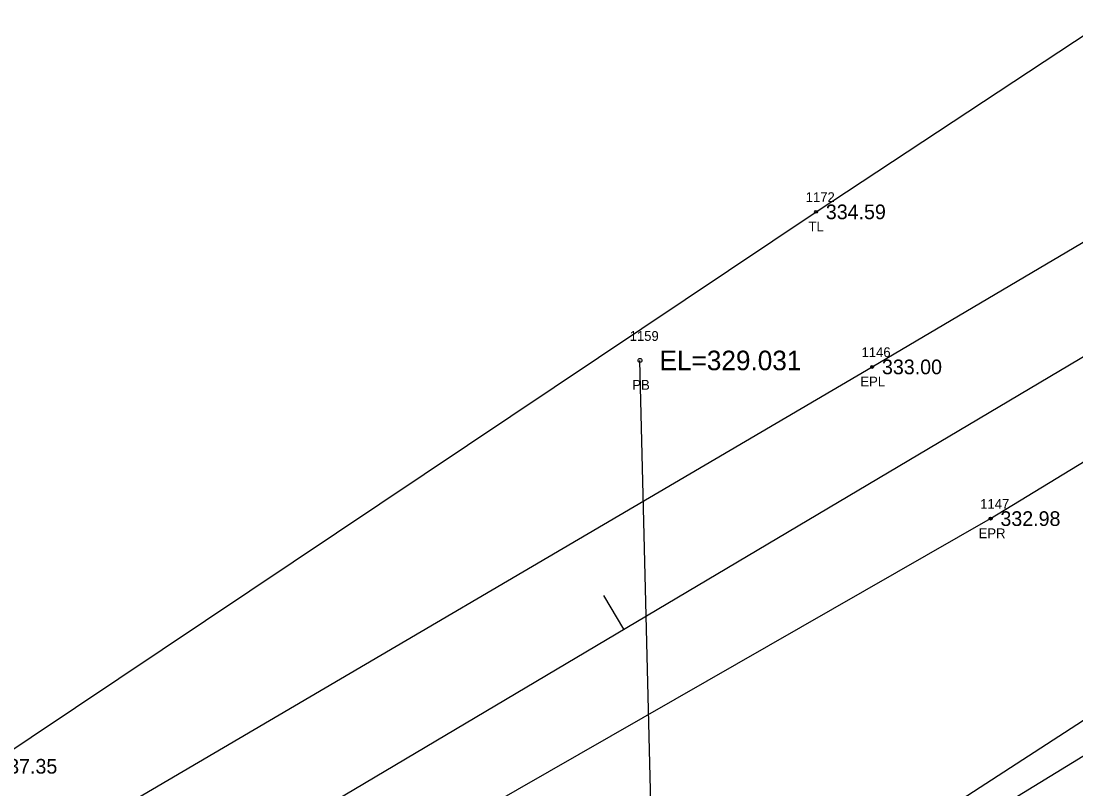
# Model space of a CAD drawing. Extents: x 2231119 to 2232595, y 1035731 to 1037094.
# Drawn here: x 2231678 to 2231785.8, y 1036525.6 to 1036604.1 of the extents above; entities that cross this region are included whole.
import ezdxf

# ---------------------------------------------------------------- set-up
doc = ezdxf.new("R2010")
doc.units = 0
for name, color, linetype in [('RD_EX_DR_Pipe', 7, 'Continuous'), ('RD_EX_DR_Pipe_txCode', 7, 'Continuous'), ('RD_EX_Fence_Other', 7, 'Continuous'), ('RD_EX_Road', 7, 'Continuous'), ('RD_EX_Road_txCode', 7, 'Continuous'), ('RD_EX_TX_Road_ELEV', 7, 'Continuous'), ('RD_EX_TX_VEG_ELEV', 7, 'Continuous'), ('RD_EX_VEG', 7, 'Continuous'), ('RD_EX_VEG_txCode', 7, 'Continuous'), ('RD_HC_Cl', 7, 'Continuous'), ('RD_HC_Data_Tic', 7, 'Continuous'), ('RD_SMD_Locator', 7, 'Continuous'), ('RD_TX_Pipe_ElevEX', 7, 'Continuous')]:
    doc.layers.add(name, color=color, linetype=linetype)

msp = doc.modelspace()

# ---------------------------------------------------------------- linework, layer by layer
at = {"layer": 'RD_EX_DR_Pipe'}
msp.add_lwpolyline([(2231761.49, 1036500.4), (2231742.72, 1036515.42), (2231742.56, 1036515.9), (2231741.25, 1036569.44)], dxfattribs=at)
at = {"layer": 'RD_EX_Fence_Other'}
msp.add_lwpolyline([(2231742.82, 1036485.51), (2231730.99, 1036494.96), (2231789.88, 1036531.02), (2231876.81, 1036583.89), (2231964.37, 1036635.23), (2232046.18, 1036684.79), (2232133.57, 1036734.4), (2232210.6, 1036793.49), (2232301.78, 1036835.03)], dxfattribs=at)
at = {"layer": 'RD_EX_Road'}
for points in [[(2231606.1, 1036462.92), (2231601.27, 1036470.82), (2231681.58, 1036519.84), (2231764.99, 1036568.78), (2231851.5, 1036619.95), (2231935.62, 1036669.65), (2232021.78, 1036720.22), (2232106.75, 1036770.57), (2232190.54, 1036819.2), (2232275.92, 1036870.27)], [(2231606.1, 1036462.92), (2231610.57, 1036455.36), (2231692.09, 1036503.24), (2231706.07, 1036512.59), (2231777.1, 1036553.27), (2231861.39, 1036604.65), (2231946.39, 1036654.77), (2232031.07, 1036704.2), (2232117.06, 1036755.16), (2232199.91, 1036803.8), (2232286.7, 1036855.36)]]:
    msp.add_lwpolyline(points, dxfattribs=at)
at = {"layer": 'RD_EX_VEG'}
for points in [[(2231598.25, 1036478.35), (2231674.54, 1036527.95), (2231759.25, 1036584.63), (2231839.99, 1036637.88), (2231924.53, 1036692.24), (2232004.98, 1036742.14), (2232090.99, 1036793.16), (2232172.16, 1036843), (2232262.27, 1036890.61)], [(2231753.59, 1036474.98), (2231730.55, 1036496.34), (2231788.45, 1036533.87), (2231871.45, 1036588.79), (2231958.94, 1036639.51), (2232040.64, 1036687.92), (2232130.59, 1036740.48), (2232213.07, 1036784.39), (2232299.54, 1036835.55)]]:
    msp.add_lwpolyline(points, dxfattribs=at)
at = {"layer": 'RD_HC_Cl'}
msp.add_line((2231548.98, 1036428.87), (2232281.06, 1036863.23), dxfattribs=at)
at = {"layer": 'RD_HC_Data_Tic'}
msp.add_line((2231739.59, 1036541.97), (2231737.55, 1036545.41), dxfattribs=at)
at = {"layer": 'RD_SMD_Locator'}
for centre, radius in [((2231759.25, 1036584.63), 0.15), ((2231741.25, 1036569.44), 0.2), ((2231764.99, 1036568.78), 0.15), ((2231777.1, 1036553.27), 0.15)]:
    msp.add_circle(centre, radius, dxfattribs=at)

# ---------------------------------------------------------------- texts
at = {"layer": 'RD_EX_DR_Pipe_txCode'}
for s, p in [('1159', (2231740.19, 1036571.44)), ('PB', (2231740.47, 1036566.44))]:
    msp.add_text(s, height=1, dxfattribs=at).set_placement(p)
at = {"layer": 'RD_EX_Road_txCode'}
for s, p in [('1146', (2231763.9, 1036569.78)), ('EPL', (2231763.78, 1036566.78)), ('1147', (2231776.03, 1036554.27)), ('EPR', (2231775.87, 1036551.27))]:
    msp.add_text(s, height=1, dxfattribs=at).set_placement(p)
at = {"layer": 'RD_EX_TX_Road_ELEV'}
for s, p in [('333.00', (2231765.99, 1036568.03)), ('332.98', (2231778.1, 1036552.52))]:
    msp.add_text(s, height=1.5, dxfattribs=at).set_placement(p)
at = {"layer": 'RD_EX_TX_VEG_ELEV'}
for s, p in [('334.59', (2231760.25, 1036583.88)), ('337.35', (2231675.54, 1036527.2))]:
    msp.add_text(s, height=1.5, dxfattribs=at).set_placement(p)
at = {"layer": 'RD_EX_VEG_txCode'}
for s, p in [('1172', (2231758.19, 1036585.63)), ('TL', (2231758.48, 1036582.63))]:
    msp.add_text(s, height=1, dxfattribs=at).set_placement(p)
at = {"layer": 'RD_TX_Pipe_ElevEX'}
msp.add_text('EL=329.031', height=2, dxfattribs=at).set_placement((2231743.25, 1036568.44))

doc.saveas('drawing.dxf')
